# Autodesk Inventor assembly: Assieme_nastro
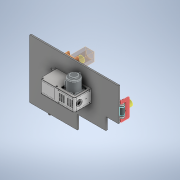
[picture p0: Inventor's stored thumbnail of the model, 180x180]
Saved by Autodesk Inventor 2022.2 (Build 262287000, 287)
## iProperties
Created: 2024-10
Part Number: Assieme_nastro
Document SubType Name: Assembly
Designer: 18907419
Title: Assieme_nastro.stp
Author: R5800u
Sending System: Autodesk Inventor 2025
Preprocessor: ST-DEVELOPER v20
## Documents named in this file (12)
- C:\Users\18907419\Desktop\automazione\nastro\Assieme_nastro.iam
- C:\Users\18907419\Desktop\automazione\nastro\SVKN-50-600-25-TA220-SCM-12_5-H-C.iam
- C:\Users\18907419\Desktop\automazione\nastro\scivolo1.ipt
- C:\Users\18907419\Desktop\automazione\nastro\piano_appoggio_nastro.ipt
- C:\Users\18907419\Desktop\automazione\nastro\magazzino_pezzo.ipt
- C:\Users\18907419\Desktop\automazione\nastro\1103200080CP_0-0-0-A-0-0.iam
- C:\Users\18907419\Desktop\automazione\nastro\pezzo.ipt
- C:\Users\18907419\Desktop\automazione\nastro\premi_pezzo.ipt
- C:\Users\18907419\Desktop\automazione\nastro\appoggio_cilindro_magazzino.ipt
- C:\Users\18907419\Desktop\automazione\nastro\blocco_pezzi_nastro.ipt
- C:\Users\18907419\Desktop\automazione\nastro\1103200080CP_0-0-0-A-0-0_1.iam
- C:\Users\18907419\Desktop\automazione\nastro\sotto_piedino_cilindro_pezzo.ipt
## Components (17 placed, 10 different names)
1. SVKN-50-600-25-TA220-SCM-12_5-H-C:1 [sub-assembly]
2. scivolo1:1
3. piano_appoggio_nastro:1
4. magazzino_pezzo:1
5. 1103200080CP_0-0-0-A-0-0:1 [sub-assembly]
6. pezzo:1
7. premi_pezzo:1
8. appoggio_cilindro_magazzino:2
9. blocco_pezzi_nastro:1
10. pezzo:2
11. pezzo:3
12. pezzo:4
13. pezzo:5
14. 1103200080CP_0-0-0-A-0-0:2 [sub-assembly]
15. premi_pezzo:2
16. appoggio_cilindro_magazzino:3
17. sotto_piedino_cilindro_pezzo:1
